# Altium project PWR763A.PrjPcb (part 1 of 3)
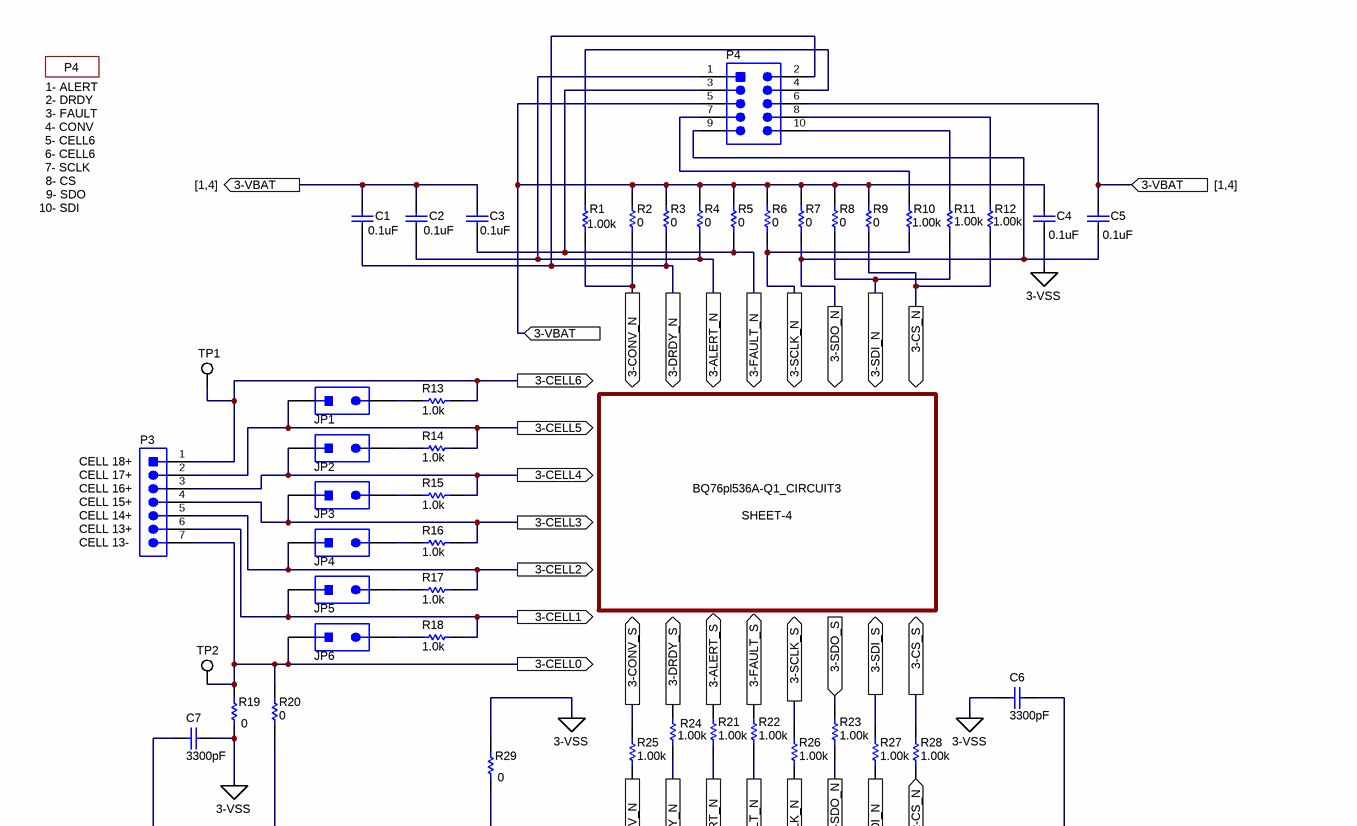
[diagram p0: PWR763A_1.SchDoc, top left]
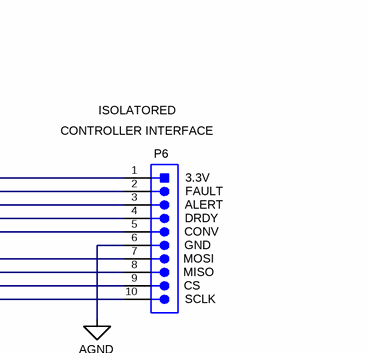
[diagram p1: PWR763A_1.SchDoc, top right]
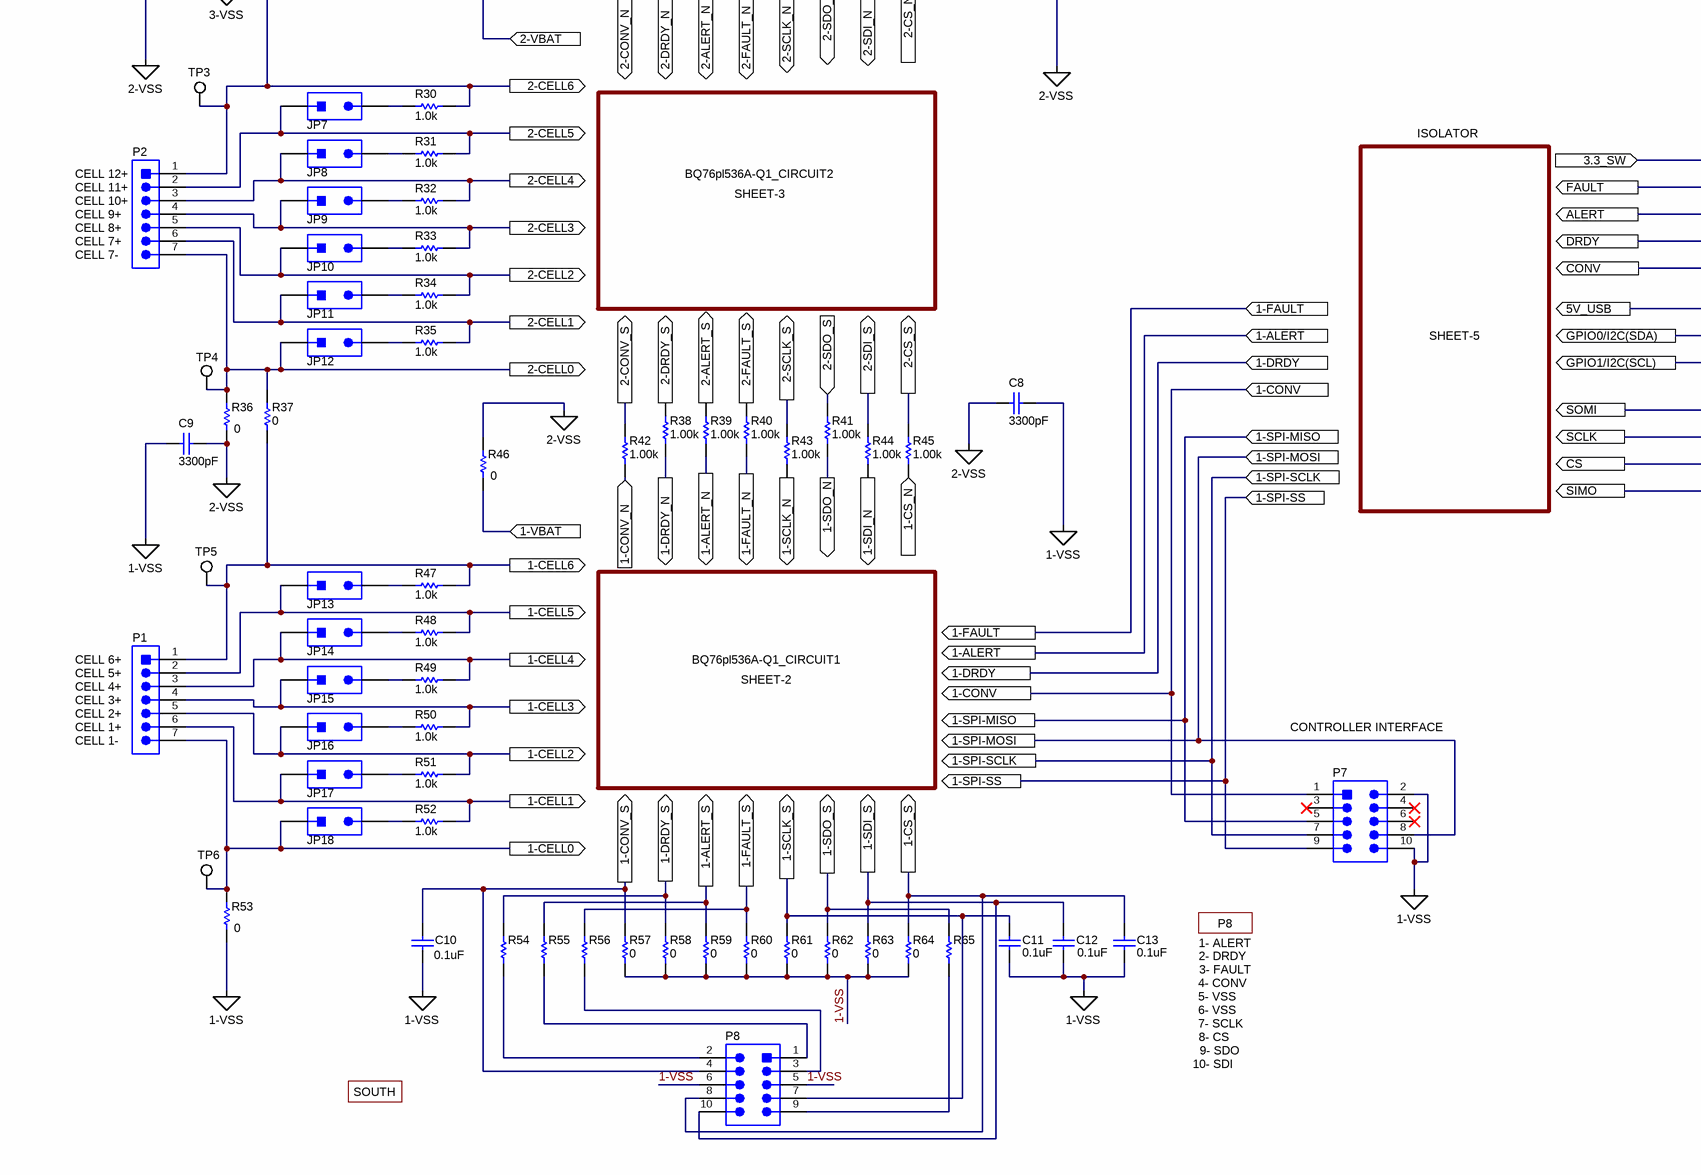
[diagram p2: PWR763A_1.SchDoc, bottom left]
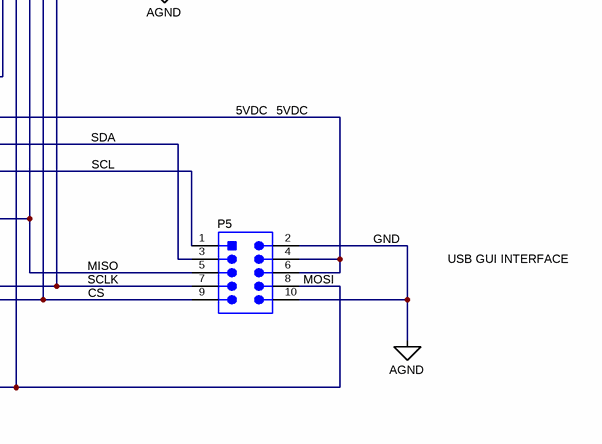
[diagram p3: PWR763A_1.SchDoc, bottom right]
TID: TID-00821; TechSupport: http://www.ti.com/support; SCH_Rev: A; PRJ_Title: PWR763; PRJ_Number: PWR763; PRJ_Engineer: Roger Hwang; PRJ_Customer: Public Release; PCB_Rev: A; PCB_Layout: Krypton-Solutions; EVM_Orderable: Bq76Pl536aQ1EVM763; CopyrightYear: 2015
6 sheets, 564 parts. Net scope: flat (ports and power ports of the same name join across sheets).
Board file: PWR763A.PcbDoc
Sheets:
  PWR763A_1.SchDoc
  PWR763A_2.SchDoc
  PWR763A_3.SchDoc
  PWR763A_4.SchDoc
  PWR763A_5.SchDoc
  PWR763A_Hardware.SchDoc

## Sheet PWR763A_1.SchDoc: PWR763A
size C; Date: Not shown in title block; ApprovedBy: Not shown in title block; CheckedBy: Not shown in title block; Author: Not shown in title block; CompanyName: Not shown in title block; Engineer: Not shown in title block; Organization: Not shown in title block; Address1: Not shown in title block; Address2: Not shown in title block; Address3: Not shown in title block; Address4: Not shown in title block; DocumentNumber: 1; Revision: Use project parameter SCH_Rev; SheetNumber: 1; SheetTotal: 6; PageSetup: Record=PageOptions¦CenterHorizontal=True¦CenterVertical=True¦PrintScale=1.00¦XCorrection=1.00¦YCorrection=1.00¦PrintKind=0¦BorderSize=5000000¦LeftOffset=0¦BottomOffset=0¦Orientation=2¦PaperLength=1000¦PaperWidth=1000¦Scale=100¦PaperSource=15¦PrintQuality=600¦MediaType=1¦DitherType=10¦PaperKind=Letter¦PrintScaleMode=1

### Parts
C1  value 0.1uF  [0603]  (hidden comment: 06035C104KAT2A)
C2  value 0.1uF  [0603]  (hidden comment: 06035C104KAT2A)
C3  value 0.1uF  [0603]  (hidden comment: 06035C104KAT2A)
C4  value 0.1uF  [0603]  (hidden comment: 06035C104KAT2A)
C5  value 0.1uF  [0603]  (hidden comment: 06035C104KAT2A)
C6  ValueDisplayed: 3300pF  [0603]  (hidden comment: GRM188R71H332KA01D)
C7  ValueDisplayed: 3300pF  [0603]  (hidden comment: GRM188R71H332KA01D)
C8  ValueDisplayed: 3300pF  [0603]  (hidden comment: GRM188R71H332KA01D)
C9  ValueDisplayed: 3300pF  [0603]  (hidden comment: GRM188R71H332KA01D)
C10  value 0.1uF  [0603]  (hidden comment: 06035C104KAT2A)
C11  value 0.1uF  [0603]  (hidden comment: 06035C104KAT2A)
C12  value 0.1uF  [0603]  (hidden comment: 06035C104KAT2A)
C13  value 0.1uF  [0603]  (hidden comment: 06035C104KAT2A)
JP1  PEC02SAAN  [CONN_PEC02SAAN]  (value not drawn)
JP2  PEC02SAAN  [CONN_PEC02SAAN]  (value not drawn)
JP3  PEC02SAAN  [CONN_PEC02SAAN]  (value not drawn)
JP4  PEC02SAAN  [CONN_PEC02SAAN]  (value not drawn)
JP5  PEC02SAAN  [CONN_PEC02SAAN]  (value not drawn)
JP6  PEC02SAAN  [CONN_PEC02SAAN]  (value not drawn)
JP7  PEC02SAAN  [CONN_PEC02SAAN]  (value not drawn)
JP8  PEC02SAAN  [CONN_PEC02SAAN]  (value not drawn)
JP9  PEC02SAAN  [CONN_PEC02SAAN]  (value not drawn)
JP10  PEC02SAAN  [CONN_PEC02SAAN]  (value not drawn)
JP11  PEC02SAAN  [CONN_PEC02SAAN]  (value not drawn)
JP12  PEC02SAAN  [CONN_PEC02SAAN]  (value not drawn)
JP13  PEC02SAAN  [CONN_PEC02SAAN]  (value not drawn)
JP14  PEC02SAAN  [CONN_PEC02SAAN]  (value not drawn)
JP15  PEC02SAAN  [CONN_PEC02SAAN]  (value not drawn)
JP16  PEC02SAAN  [CONN_PEC02SAAN]  (value not drawn)
JP17  PEC02SAAN  [CONN_PEC02SAAN]  (value not drawn)
JP18  PEC02SAAN  [CONN_PEC02SAAN]  (value not drawn)
P1  395021007  [Molex_395021007]  (value not drawn)
P2  395021007  [Molex_395021007]  (value not drawn)
P3  395021007  [Molex_395021007]  (value not drawn)
P4  5103308-1  [CONN_5103308-1]  (value not drawn)
P5  5103308-1  [CONN_5103308-1]  (value not drawn)
P6  HPM-10-05-T-S  [Samtec_HPM-10-05-T-S]  (value not drawn)
P7  5103308-1  [CONN_5103308-1]  (value not drawn)
P8  5103308-1  [CONN_5103308-1]  (value not drawn)
R1  value 1.00k  [1206]  (hidden comment: CRCW12061K00FKEA)
R2  ValueDisplayed: 0  [0603]  (hidden comment: CRCW06030000Z0EA)
R3  ValueDisplayed: 0  [0603]  (hidden comment: CRCW06030000Z0EA)
R4  ValueDisplayed: 0  [0603]  (hidden comment: CRCW06030000Z0EA)
R5  ValueDisplayed: 0  [0603]  (hidden comment: CRCW06030000Z0EA)
R6  ValueDisplayed: 0  [0603]  (hidden comment: CRCW06030000Z0EA)
R7  ValueDisplayed: 0  [0603]  (hidden comment: CRCW06030000Z0EA)
R8  ValueDisplayed: 0  [0603]  (hidden comment: CRCW06030000Z0EA)
R9  ValueDisplayed: 0  [0603]  (hidden comment: CRCW06030000Z0EA)
R10  value 1.00k  [1206]  (hidden comment: CRCW12061K00FKEA)
R11  value 1.00k  [1206]  (hidden comment: CRCW12061K00FKEA)
R12  value 1.00k  [1206]  (hidden comment: CRCW12061K00FKEA)
R13  ValueDisplayed: 1.0k  [0603]  (hidden comment: CRCW06031K00JNEA)
R14  ValueDisplayed: 1.0k  [0603]  (hidden comment: CRCW06031K00JNEA)
R15  ValueDisplayed: 1.0k  [0603]  (hidden comment: CRCW06031K00JNEA)
R16  ValueDisplayed: 1.0k  [0603]  (hidden comment: CRCW06031K00JNEA)
R17  ValueDisplayed: 1.0k  [0603]  (hidden comment: CRCW06031K00JNEA)
R18  ValueDisplayed: 1.0k  [0603]  (hidden comment: CRCW06031K00JNEA)
R19  ValueDisplayed: 0  [1206]  (hidden comment: CRCW12060000Z0EA)
R20  ValueDisplayed: 0  [0603]  (hidden comment: CRCW06030000Z0EA)
R21  ValueDisplayed: 1.00k  [0603]  (hidden comment: RG1608P-102-B-T5)
R22  ValueDisplayed: 1.00k  [0603]  (hidden comment: RG1608P-102-B-T5)
R23  ValueDisplayed: 1.00k  [0603]  (hidden comment: RG1608P-102-B-T5)
R24  ValueDisplayed: 1.00k  [0603]  (hidden comment: RG1608P-102-B-T5)
R25  ValueDisplayed: 1.00k  [0603]  (hidden comment: RG1608P-102-B-T5)
R26  ValueDisplayed: 1.00k  [0603]  (hidden comment: RG1608P-102-B-T5)
R27  ValueDisplayed: 1.00k  [0603]  (hidden comment: RG1608P-102-B-T5)
R28  ValueDisplayed: 1.00k  [0603]  (hidden comment: RG1608P-102-B-T5)
R29  ValueDisplayed: 0  [1206]  (hidden comment: CRCW12060000Z0EA)
R30  ValueDisplayed: 1.0k  [0603]  (hidden comment: CRCW06031K00JNEA)
R31  ValueDisplayed: 1.0k  [0603]  (hidden comment: CRCW06031K00JNEA)
R32  ValueDisplayed: 1.0k  [0603]  (hidden comment: CRCW06031K00JNEA)
R33  ValueDisplayed: 1.0k  [0603]  (hidden comment: CRCW06031K00JNEA)
R34  ValueDisplayed: 1.0k  [0603]  (hidden comment: CRCW06031K00JNEA)
R35  ValueDisplayed: 1.0k  [0603]  (hidden comment: CRCW06031K00JNEA)
R36  ValueDisplayed: 0  [1206]  (hidden comment: CRCW12060000Z0EA)
R37  ValueDisplayed: 0  [0603]  (hidden comment: CRCW06030000Z0EA)
R38  ValueDisplayed: 1.00k  [0603]  (hidden comment: RG1608P-102-B-T5)
R39  ValueDisplayed: 1.00k  [0603]  (hidden comment: RG1608P-102-B-T5)
R40  ValueDisplayed: 1.00k  [0603]  (hidden comment: RG1608P-102-B-T5)
R41  ValueDisplayed: 1.00k  [0603]  (hidden comment: RG1608P-102-B-T5)
R42  ValueDisplayed: 1.00k  [0603]  (hidden comment: RG1608P-102-B-T5)
R43  ValueDisplayed: 1.00k  [0603]  (hidden comment: RG1608P-102-B-T5)
R44  ValueDisplayed: 1.00k  [0603]  (hidden comment: RG1608P-102-B-T5)
R45  ValueDisplayed: 1.00k  [0603]  (hidden comment: RG1608P-102-B-T5)
R46  ValueDisplayed: 0  [1206]  (hidden comment: CRCW12060000Z0EA)
R47  ValueDisplayed: 1.0k  [0603]  (hidden comment: CRCW06031K00JNEA)
R48  ValueDisplayed: 1.0k  [0603]  (hidden comment: CRCW06031K00JNEA)
R49  ValueDisplayed: 1.0k  [0603]  (hidden comment: CRCW06031K00JNEA)
R50  ValueDisplayed: 1.0k  [0603]  (hidden comment: CRCW06031K00JNEA)
R51  ValueDisplayed: 1.0k  [0603]  (hidden comment: CRCW06031K00JNEA)
R52  ValueDisplayed: 1.0k  [0603]  (hidden comment: CRCW06031K00JNEA)
R53  ValueDisplayed: 0  [1206]  (hidden comment: CRCW12060000Z0EA)
R54  CRCW12061K00FKEA  [1206]  (value not drawn)
R55  CRCW12061K00FKEA  [1206]  (value not drawn)
R56  CRCW12061K00FKEA  [1206]  (value not drawn)
R57  ValueDisplayed: 0  [0603]  (hidden comment: CRCW06030000Z0EA)
R58  ValueDisplayed: 0  [0603]  (hidden comment: CRCW06030000Z0EA)
R59  ValueDisplayed: 0  [0603]  (hidden comment: CRCW06030000Z0EA)
R60  ValueDisplayed: 0  [0603]  (hidden comment: CRCW06030000Z0EA)
R61  ValueDisplayed: 0  [0603]  (hidden comment: CRCW06030000Z0EA)
R62  ValueDisplayed: 0  [0603]  (hidden comment: CRCW06030000Z0EA)
R63  ValueDisplayed: 0  [0603]  (hidden comment: CRCW06030000Z0EA)
R64  ValueDisplayed: 0  [0603]  (hidden comment: CRCW06030000Z0EA)
R65  CRCW12061K00FKEA  [1206]  (value not drawn)
TP1  5015  [Testpoint_Keystone_Miniature]  (value not drawn)
TP2  5015  [Testpoint_Keystone_Miniature]  (value not drawn)
TP3  5015  [Testpoint_Keystone_Miniature]  (value not drawn)
TP4  5015  [Testpoint_Keystone_Miniature]  (value not drawn)
TP5  5015  [Testpoint_Keystone_Miniature]  (value not drawn)
TP6  5015  [Testpoint_Keystone_Miniature]  (value not drawn)

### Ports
1-ALERT, 1-ALERT_N, 1-ALERT_S, 1-CELL0, 1-CELL1, 1-CELL2, 1-CELL3, 1-CELL4, 1-CELL5, 1-CELL6, 1-CONV, 1-CONV_N (in), 1-CONV_S, 1-CS_N, 1-CS_S, 1-DRDY, 1-DRDY_N, 1-DRDY_S, 1-FAULT, 1-FAULT_N, 1-FAULT_S, 1-SCLK_N (in), 1-SCLK_S, 1-SDI_N (in), 1-SDI_S, 1-SDO_N (out), 1-SDO_S, 1-SPI-MISO, 1-SPI-MOSI, 1-SPI-SCLK, 1-SPI-SS, 1-VBAT, 2-ALERT_N, 2-ALERT_S (in), 2-CELL0, 2-CELL1, 2-CELL2, 2-CELL3, 2-CELL4, 2-CELL5, 2-CELL6, 2-CONV_N (in), 2-CONV_S, 2-CS_N (in), 2-CS_S, 2-DRDY_N, 2-DRDY_S (in), 2-FAULT_N, 2-FAULT_S (in), 2-SCLK_N (in), 2-SCLK_S, 2-SDI_N (in), 2-SDI_S, 2-SDO_N (out), 2-SDO_S (in), 2-VBAT, 3-ALERT_N, 3-ALERT_S (in), 3-CELL0, 3-CELL1, 3-CELL2, 3-CELL3, 3-CELL4, 3-CELL5, 3-CELL6, 3-CONV_N, 3-CONV_S, 3-CS_N (out), 3-CS_S, 3-DRDY_N, 3-DRDY_S (in), 3-FAULT_N, 3-FAULT_S (in), 3-SCLK_N (out), 3-SCLK_S, 3-SDI_N, 3-SDI_S, 3-SDO_N (out), 3-SDO_S (in), 3-VBAT, 3.3_SW, 5V_USB, ALERT, CONV, CS, DRDY, FAULT, GPIO0/I2C(SDA), GPIO1/I2C(SCL), SCLK, SIMO, SOMI

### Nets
1-VSS: C8.1 C9.2 C10.2 C11.2 C12.2 C13.2 JP18.1 P1.7 P7.2 P7.10 P8.5 P8.6 R53.1 R53.2 R57.1 R58.1 R59.1 R60.1 R61.1 R62.1 R63.1 R64.1 TP6.1 ; port 1-CELL0  [project net 1-VC0]
2-VSS: C6.1 C7.2 C8.2 C9.1 JP12.1 P2.7 R36.1 R36.2 R37.2 R46.2 TP4.1 ; port 2-CELL0  [project net 2-VC0]
3-VSS: C4.2 C6.2 C7.1 JP6.1 P3.7 R19.1 R19.2 R20.2 R29.2 TP2.1 ; port 3-CELL0  [project net 3-VC0]
AGND: P5.2 P5.10 P6.6
1-ALERT_N: R39.1 ; port 1-ALERT_N
1-ALERT_S: R55.2 R59.2 ; port 1-ALERT_S
1-CELL1: JP17.1 P1.6 R52.2 ; port 1-CELL1
1-CELL2: JP16.1 P1.5 R51.2 ; port 1-CELL2
1-CELL3: JP15.1 P1.4 R50.2 ; port 1-CELL3
1-CELL4: JP14.1 P1.3 R49.2 ; port 1-CELL4
1-CELL5: JP13.1 P1.2 R48.2 ; port 1-CELL5
1-CELL6: P1.1 R37.1 R47.2 TP5.1 ; port 1-CELL6
1-CONV: P7.1 ; port 1-CONV
1-CONV_N: R42.1 ; port 1-CONV_N
1-CONV_S: C10.1 P8.4 R57.2 ; port 1-CONV_S
1-CS_N: R45.1 ; port 1-CS_N
1-CS_S: C13.1 P8.8 R64.2 ; port 1-CS_S
1-DRDY_N: R38.1 ; port 1-DRDY_N
1-DRDY_S: R54.2 R58.2 ; port 1-DRDY_S
1-FAULT_N: R40.1 ; port 1-FAULT_N
1-FAULT_S: R56.2 R60.2 ; port 1-FAULT_S
1-SCLK_N: R43.1 ; port 1-SCLK_N
1-SCLK_S: C11.1 P8.7 R61.2 ; port 1-SCLK_S
1-SDI_N: R44.1 ; port 1-SDI_N
1-SDI_S: C12.1 P8.10 R63.2 ; port 1-SDI_S
1-SDO_N: R41.1 ; port 1-SDO_N
1-SDO_S: R62.2 R65.2 ; port 1-SDO_S
1-SPI-MISO: P7.5 ; port 1-SPI-MISO
1-SPI-MOSI: P7.8 ; port 1-SPI-MOSI
1-SPI-SCLK: P7.7 ; port 1-SPI-SCLK
1-SPI-SS: P7.9 ; port 1-SPI-SS
1-VBAT: R46.1 ; port 1-VBAT
2-ALERT_N: R21.1 ; port 2-ALERT_N
2-ALERT_S: R39.2 ; port 2-ALERT_S
2-CELL1: JP11.1 P2.6 R35.2 ; port 2-CELL1
2-CELL2: JP10.1 P2.5 R34.2 ; port 2-CELL2
2-CELL3: JP9.1 P2.4 R33.2 ; port 2-CELL3
2-CELL4: JP8.1 P2.3 R32.2 ; port 2-CELL4
2-CELL5: JP7.1 P2.2 R31.2 ; port 2-CELL5
2-CELL6: P2.1 R20.1 R30.2 TP3.1 ; port 2-CELL6
2-CONV_N: R25.1 ; port 2-CONV_N
2-CONV_S: R42.2 ; port 2-CONV_S
2-CS_N: R28.1 ; port 2-CS_N
2-CS_S: R45.2 ; port 2-CS_S
2-DRDY_N: R24.1 ; port 2-DRDY_N
2-DRDY_S: R38.2 ; port 2-DRDY_S
2-FAULT_N: R22.1 ; port 2-FAULT_N
2-FAULT_S: R40.2 ; port 2-FAULT_S
2-SCLK_N: R26.1 ; port 2-SCLK_N
2-SCLK_S: R43.2 ; port 2-SCLK_S
2-SDI_N: R27.1 ; port 2-SDI_N
2-SDI_S: R44.2 ; port 2-SDI_S
2-SDO_N: R23.1 ; port 2-SDO_N
2-SDO_S: R41.2 ; port 2-SDO_S
2-VBAT: R29.1 ; port 2-VBAT
3-ALERT_N: C2.2 P4.1 R4.1 ; port 3-ALERT_N
3-ALERT_S: R21.2 ; port 3-ALERT_S
3-CELL1: JP5.1 P3.6 R18.2 ; port 3-CELL1
3-CELL2: JP4.1 P3.5 R17.2 ; port 3-CELL2
3-CELL3: JP3.1 P3.4 R16.2 ; port 3-CELL3
3-CELL4: JP2.1 P3.3 R15.2 ; port 3-CELL4
3-CELL5: JP1.1 P3.2 R14.2 ; port 3-CELL5
3-CELL6: P3.1 R13.2 TP1.1 ; port 3-CELL6
3-CONV_N: R1.1 R2.1 ; port 3-CONV_N
3-CONV_S: R25.2 ; port 3-CONV_S
3-CS_N: R9.1 R12.1 ; port 3-CS_N
3-CS_S: R28.2 ; port 3-CS_S
3-DRDY_N: C1.2 P4.2 R3.1 ; port 3-DRDY_N
3-DRDY_S: R24.2 ; port 3-DRDY_S
3-FAULT_N: C3.2 P4.3 R5.1 ; port 3-FAULT_N
3-FAULT_S: R22.2 ; port 3-FAULT_S
3-SCLK_N: R6.1 R10.1 ; port 3-SCLK_N
3-SCLK_S: R26.2 ; port 3-SCLK_S
3-SDI_N: R8.1 R11.1 ; port 3-SDI_N
3-SDI_S: R27.2 ; port 3-SDI_S
3-SDO_N: C5.2 P4.9 R7.1 ; port 3-SDO_N
3-SDO_S: R23.2 ; port 3-SDO_S
3-VBAT: C1.1 C2.1 C3.1 C4.1 C5.1 P4.5 P4.6 R2.2 R3.2 R4.2 R5.2 R6.2 R7.2 R8.2 R9.2 ; port 3-VBAT
3.3_SW: P6.1 ; port 3.3_SW
5V_USB: P5.4 P5.6 ; port 5V_USB
ALERT: P6.3 ; port ALERT
CONV: P6.5 ; port CONV
CS: P5.9 P6.9 ; port CS
DRDY: P6.4 ; port DRDY
FAULT: P6.2 ; port FAULT
GPIO0/I2C(SDA): P5.3 ; port GPIO0/I2C(SDA)
GPIO1/I2C(SCL): P5.1 ; port GPIO1/I2C(SCL)
SCLK: P5.7 P6.10 ; port SCLK
SIMO: P5.8 P6.7 ; port SIMO
SOMI: P5.5 P6.8 ; port SOMI
NetJP1_2: JP1.2 R13.1
NetJP2_2: JP2.2 R14.1
NetJP3_2: JP3.2 R15.1
NetJP4_2: JP4.2 R16.1
NetJP5_2: JP5.2 R17.1
NetJP6_2: JP6.2 R18.1
NetJP7_2: JP7.2 R30.1
NetJP8_2: JP8.2 R31.1
NetJP9_2: JP9.2 R32.1
NetJP10_2: JP10.2 R33.1
NetJP11_2: JP11.2 R34.1
NetJP12_2: JP12.2 R35.1
NetJP13_2: JP13.2 R47.1
NetJP14_2: JP14.2 R48.1
NetJP15_2: JP15.2 R49.1
NetJP16_2: JP16.2 R50.1
NetJP17_2: JP17.2 R51.1
NetJP18_2: JP18.2 R52.1
NetP4_4: P4.4 R1.2
NetP4_7: P4.7 R10.2
NetP4_8: P4.8 R12.2
NetP4_10: P4.10 R11.2
NetP8_1: P8.1 R55.1
NetP8_2: P8.2 R54.1
NetP8_3: P8.3 R56.1
NetP8_9: P8.9 R65.1

Not connected (* = marked no-connect by the designer): P7 3* 4* 6*

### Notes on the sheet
- P4
- 2- DRDY
- 4- CONV
- 5- CELL6
- 1- ALERT
- 3- FAULT
- 10- SDI
- 8- CS
- 9- SDO
- 7- SCLK
- 6- CELL6
- [1,4]
- (near P3) CELL 17+
- (near P3) CELL 18+
- (near P3) CELL 13-
- (near P3) CELL 13+
- (near P3) CELL 14+
- (near P3) CELL 15+
- (near P3) CELL 16+
- BQ76pl536A-Q1_CIRCUIT3
- SHEET-4
- ISOLATORED
- (near P6) CONTROLLER INTERFACE
- (near P6) 3.3V
- (near P6) DRDY
- (near P6) CONV
- (near P6) FAULT
- (near P6) ALERT
- ISOLATOR
- (near P6) CS
- (near P6) GND
- (near P6) MOSI
- (near P6) MISO
- (near P6) SCLK
- (near P2) CELL 8+
- (near P2) CELL 9+
- (near P2) CELL 10+
- (near P2) CELL 11+
- (near P2) CELL 12+
- BQ76pl536A-Q1_CIRCUIT2
- SHEET-3
- (near P2) CELL 7-
- (near P2) CELL 7+
- 5VDC
- SHEET-5
- SCL
- SDA
- GND
- CS
- SCLK
- MISO
- (near P5) MOSI
- USB GUI INTERFACE
- (near P1) CELL 3+
- (near P1) CELL 4+
- (near P1) CELL 5+
- (near P1) CELL 6+
- BQ76pl536A-Q1_CIRCUIT1
- SHEET-2
- (near P1) CELL 1-
- (near P1) CELL 1+
- (near P1) CELL 2+
- CONTROLLER INTERFACE
- P8
- 5- VSS
- 6- VSS
- SOUTH

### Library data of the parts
C1-C5 C10-C13 = 06035C104KAT2A: CAP, CERM, 0.1 µF, 50 V, +/- 10%, X7R, 0603; Manufacturer: AVX; Polarized: N; CompType: Capacitor; ValueDisplayed: 0.1µF; U/M: EA; Cap_F: 0.0000001; Tolerance_%: 10; Value1: Unknown; VDC_V: 50; Value2: 50V; TaMin_C: -55; TaMax_C: 125
C6-C9 = GRM188R71H332KA01D: CAP, CERM, 3300 pF, 50 V, +/- 10%, X7R, 0603; Manufacturer: MuRata; Polarized: N; CompType: Capacitor; Value: 3300pF; U/M: EA; Cap_F: 0.0000000033; Tolerance_%: 10; Value1: Unknown; VDC_V: 50; Value2: 50V; TaMin_C: -55; TaMax_C: 125
JP1-JP18 = PEC02SAAN: Header, 100mil, 2x1, Tin, TH; Manufacturer: Sullins Connector Solutions; SymbolCreator: a0412235; U/M: EA
P1-P3 = 395021007: Header(Shrouded), 3.5mm, 7x1,  R/A, TH; Manufacturer: Molex; SymbolCreator: a0411947; U/M: EA
P4 P5 P7 P8 = 5103308-1: Header (shrouded), 100mil, 5x2, Gold, TH; Manufacturer: TE Connectivity; SymbolCreator: a0412235; U/M: EA
P6 = HPM-10-05-T-S: Header, 5.08mm, 10x1, Tin, TH; Manufacturer: Samtec; SymbolCreator: a0412235; U/M: EA
R1 R10-R12 = CRCW12061K00FKEA: RES, 1.00 k, 1%, 0.25 W, 1206; Manufacturer: Vishay-Dale; CompType: Resistor; Res_ohm: 1000; Value_Code: 1k00; Tolerance_%: 1; Power_W: 0.25; Value2: 0.25W; VDC_V: 200; TempCo: 100 ppm/C; EIA_Code: E96; U/M: EA
R2-R9 R20 R37 R57-R64 = CRCW06030000Z0EA: RES, 0, 5%, 0.1 W, 0603; Manufacturer: Vishay-Dale; CompType: Resistor; Value: 0; Value_Code: 0000; Tolerance_%: 5; Power_W: 0.1; Value2: 0.1W; VDC_V: 75; TempCo: 200 ppm/C; EIA_Code: E24; U/M: EA
R13-R18 R30-R35 R47-R52 = CRCW06031K00JNEA: RES, 1.0 k, 5%, 0.1 W, 0603; Manufacturer: Vishay-Dale; CompType: Resistor; Value: 1.0k; Res_ohm: 1000; Value_Code: 1k00; Tolerance_%: 5; Power_W: 0.1; Value2: 0.1W; VDC_V: 75; TempCo: 200 ppm/C; EIA_Code: E24; U/M: EA
R19 R29 R36 R46 R53 = CRCW12060000Z0EA: RES, 0, 5%, 0.25 W, 1206; Manufacturer: Vishay-Dale; CompType: Resistor; Value: 0; Value_Code: 0000; Tolerance_%: 5; Power_W: 0.25; Value2: 0.25W; VDC_V: 200; TempCo: 200 ppm/C; EIA_Code: E24; U/M: EA
R21-R28 R38-R45 = RG1608P-102-B-T5: RES, 1.00 k, 0.1%, 0.1 W, 0603; Manufacturer: Susumu Co Ltd; CompType: Resistor; Value: 1.00k; Res_ohm: 1000; Value_Code: 1k00; Tolerance_%: 0.1; Value2: 0.1W; VDC_V: 75; TempCo: 25 ppm/C; EIA_Code: E192; U/M: EA
R54-R56 R65 = CRCW12061K00FKEA: RES, 1.00 k, 1%, 0.25 W, 1206; Manufacturer: Vishay-Dale; CompType: Resistor; Value: 1.00k; Res_ohm: 1000; Value_Code: 1k00; Tolerance_%: 1; Power_W: 0.25; Value2: 0.25W; VDC_V: 200; TempCo: 100 ppm/C; EIA_Code: E96; U/M: EA
TP1-TP6 = 5015: Test Point, Miniature, SMT; Manufacturer: Keystone; CompType: Test Point Loop; U/M: EA

## Sheet PWR763A_2.SchDoc: PWR763A
size 431 x 279 mm; Date: Not shown in title block; ApprovedBy: Not shown in title block; CheckedBy: Not shown in title block; Author: Not shown in title block; CompanyName: Not shown in title block; Engineer: Not shown in title block; Organization: Not shown in title block; Address1: Not shown in title block; Address2: Not shown in title block; Address3: Not shown in title block; Address4: Not shown in title block; DocumentNumber: 1; Revision: Use project parameter SCH_Rev; SheetNumber: 2; SheetTotal: 6; PageSetup: Record=PageOptions¦CenterHorizontal=True¦CenterVertical=True¦PrintScale=1.00¦XCorrection=1.00¦YCorrection=1.00¦PrintKind=0¦BorderSize=5000000¦LeftOffset=0¦BottomOffset=0¦Orientation=2¦PaperLength=1000¦PaperWidth=1000¦Scale=100¦PaperSource=15¦PrintQuality=600¦MediaType=1¦DitherType=10¦PaperKind=Letter¦PrintScaleMode=1
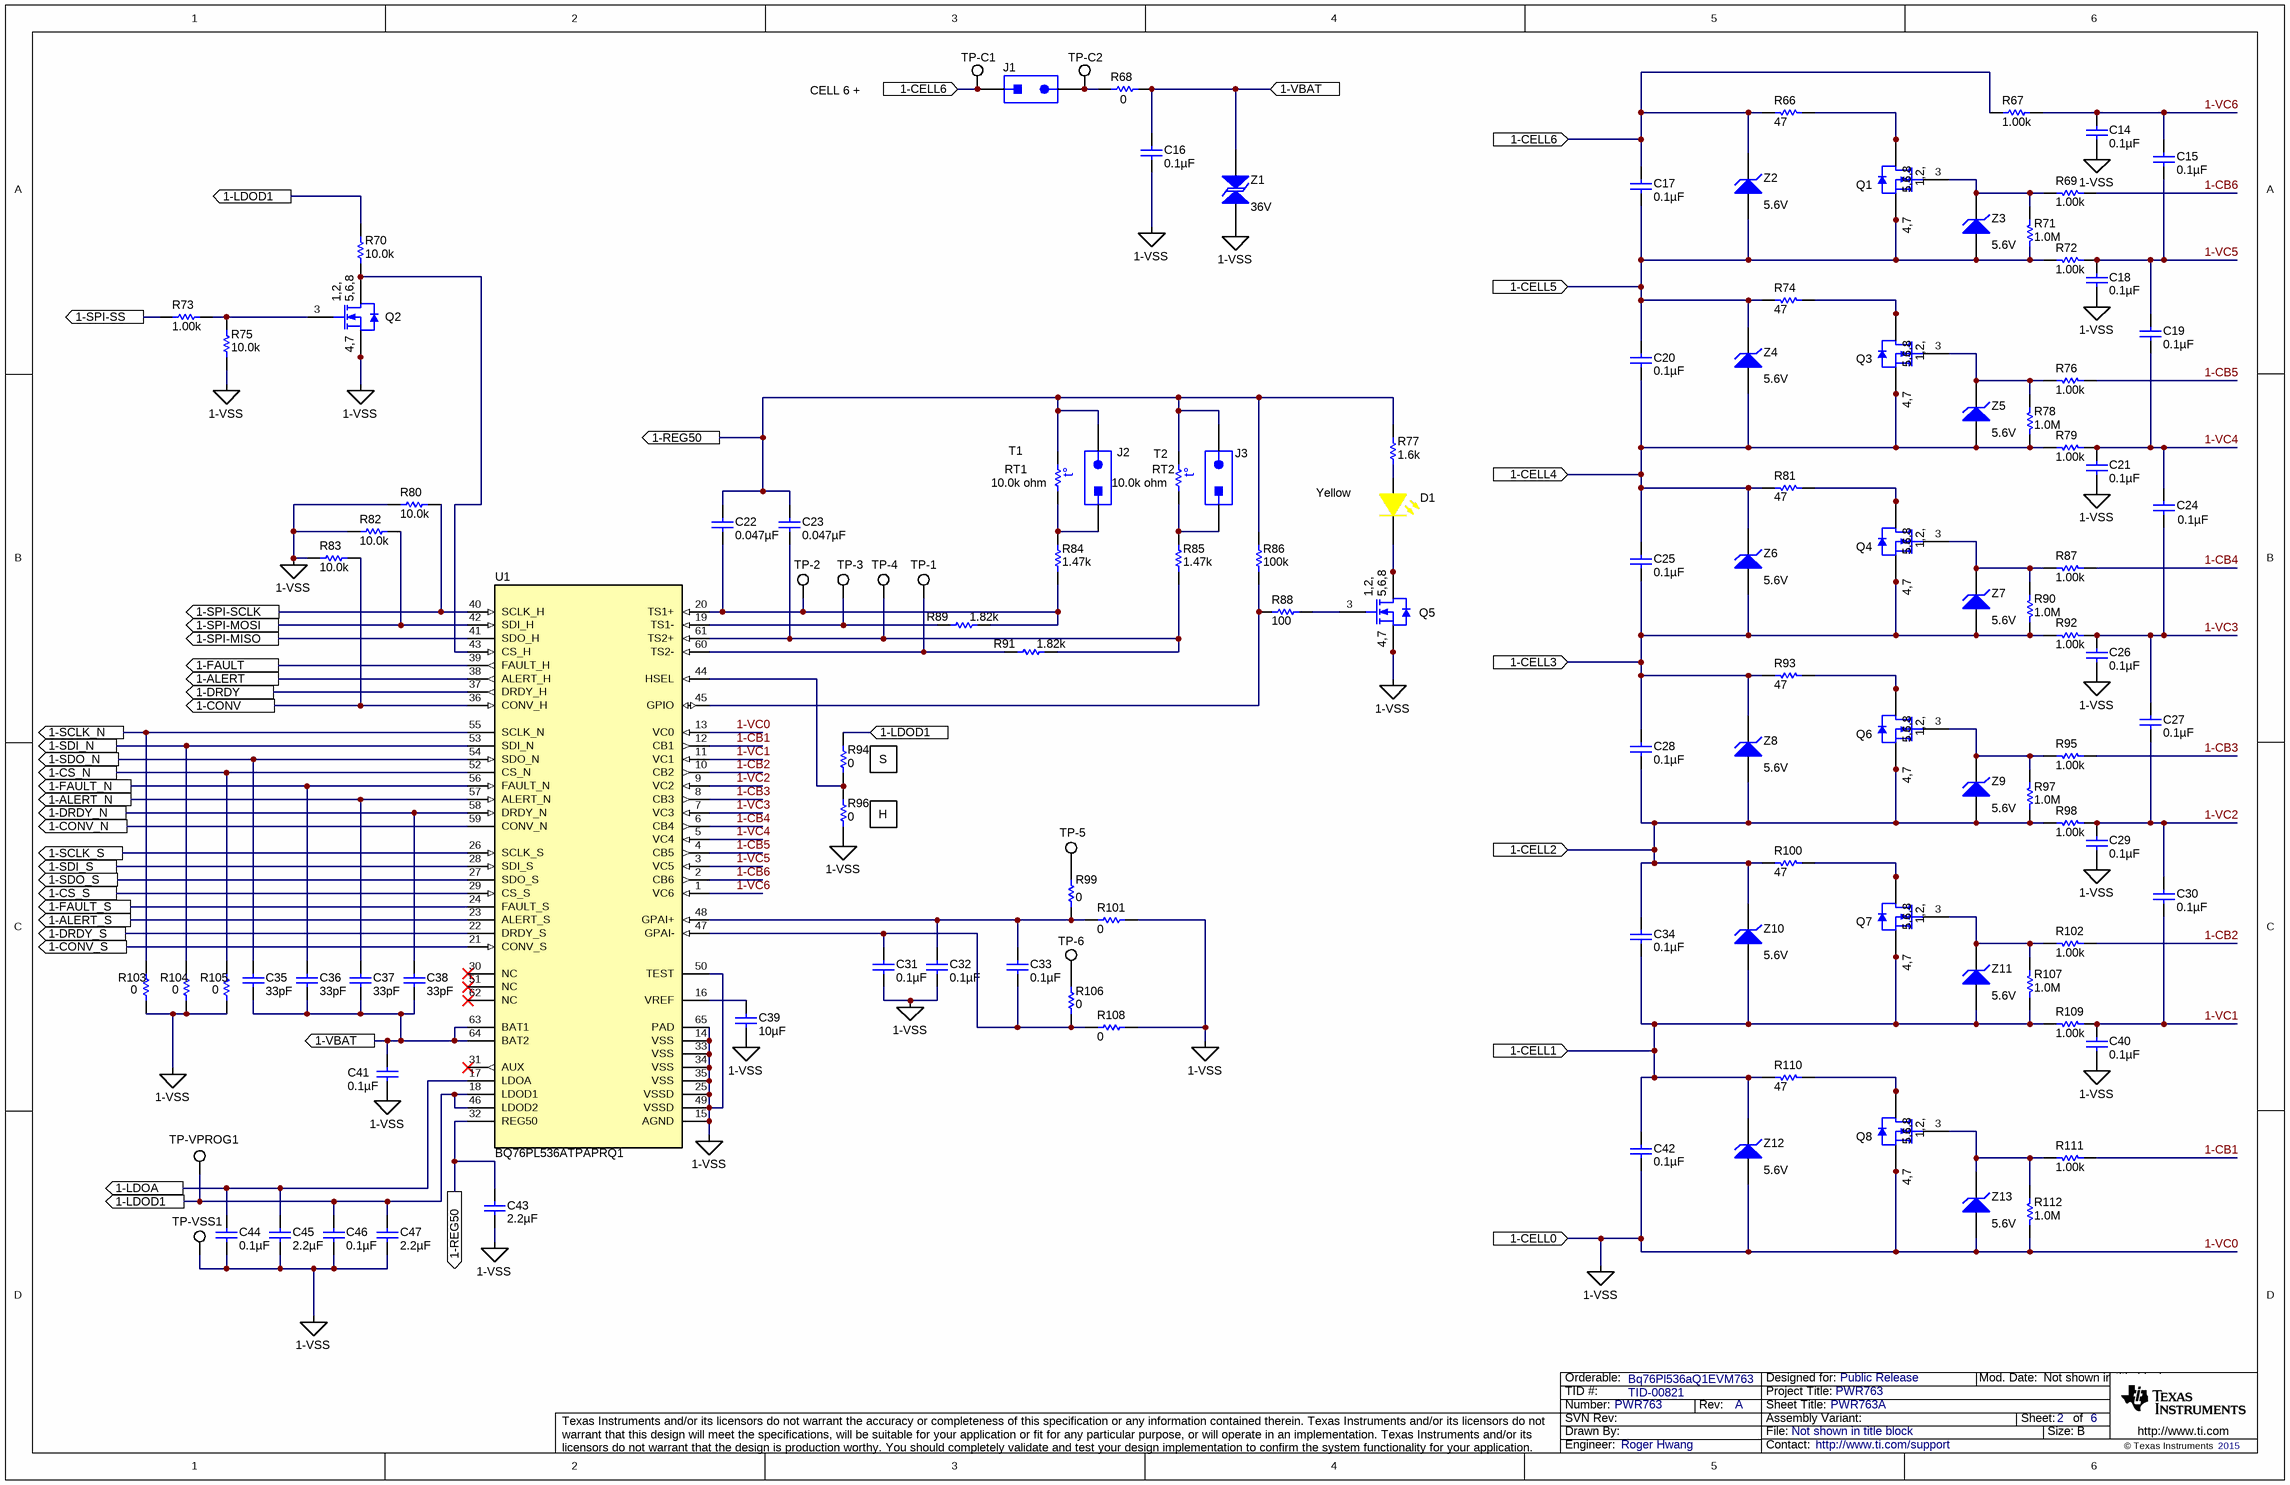
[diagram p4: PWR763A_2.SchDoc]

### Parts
C14  ValueDisplayed: 0.1µF  [0603]  (hidden comment: 06035C104KAT2A)
C15  ValueDisplayed: 0.1µF  [0603]  (hidden comment: GRM188R72A104KA35D)
C16  ValueDisplayed: 0.1µF  [0603]  (hidden comment: GRM188R72A104KA35D)
C17  ValueDisplayed: 0.1µF  [0603]  (hidden comment: 06035C104KAT2A)
C18  ValueDisplayed: 0.1µF  [0603]  (hidden comment: 06035C104KAT2A)
C19  ValueDisplayed: 0.1µF  [0603]  (hidden comment: GRM188R72A104KA35D)
C20  ValueDisplayed: 0.1µF  [0603]  (hidden comment: 06035C104KAT2A)
C21  ValueDisplayed: 0.1µF  [0603]  (hidden comment: 06035C104KAT2A)
C22  ValueDisplayed: 0.047µF  [0603]  (hidden comment: GRM188R71C473KA01D)
C23  ValueDisplayed: 0.047µF  [0603]  (hidden comment: GRM188R71C473KA01D)
C24  ValueDisplayed: 0.1µF  [0603]  (hidden comment: GRM188R72A104KA35D)
C25  ValueDisplayed: 0.1µF  [0603]  (hidden comment: 06035C104KAT2A)
C26  ValueDisplayed: 0.1µF  [0603]  (hidden comment: 06035C104KAT2A)
C27  ValueDisplayed: 0.1µF  [0603]  (hidden comment: GRM188R72A104KA35D)
C28  ValueDisplayed: 0.1µF  [0603]  (hidden comment: 06035C104KAT2A)
C29  ValueDisplayed: 0.1µF  [0603]  (hidden comment: 06035C104KAT2A)
C30  ValueDisplayed: 0.1µF  [0603]  (hidden comment: GRM188R72A104KA35D)
C31  ValueDisplayed: 0.1µF  [0603]  (hidden comment: C0603C104K4RACTU)
C32  ValueDisplayed: 0.1µF  [0603]  (hidden comment: C0603C104K4RACTU)
C33  ValueDisplayed: 0.1µF  [0603]  (hidden comment: C0603C104K4RACTU)
C34  ValueDisplayed: 0.1µF  [0603]  (hidden comment: GRM188R72A104KA35D)
C35  ValueDisplayed: 33pF  [0603]  (hidden comment: GRM1885C1H330JA01D)
C36  ValueDisplayed: 33pF  [0603]  (hidden comment: GRM1885C1H330JA01D)
C37  ValueDisplayed: 33pF  [0603]  (hidden comment: GRM1885C1H330JA01D)
C38  ValueDisplayed: 33pF  [0603]  (hidden comment: GRM1885C1H330JA01D)
C39  ValueDisplayed: 10µF  [0805_145]  (hidden comment: C2012X7R1A106M125AC)
C40  ValueDisplayed: 0.1µF  [0603]  (hidden comment: 06035C104KAT2A)
C41  ValueDisplayed: 0.1µF  [0603]  (hidden comment: 06035C104KAT2A)
C42  ValueDisplayed: 0.1µF  [0603]  (hidden comment: 06035C104KAT2A)
C43  ValueDisplayed: 2.2µF  [0805_HV]  (hidden comment: GRM21BR71A225KA01L)
C44  ValueDisplayed: 0.1µF  [0603]  (hidden comment: 06035C104KAT2A)
C45  ValueDisplayed: 2.2µF  [0805_HV]  (hidden comment: GRM21BR71A225KA01L)
C46  ValueDisplayed: 0.1µF  [0603]  (hidden comment: 06035C104KAT2A)
C47  ValueDisplayed: 2.2µF  [0805_HV]  (hidden comment: GRM21BR71A225KA01L)
D1  value Yellow  [APT1608_Yellow]  (hidden comment: APT1608SYCK)
J1  PEC02SAAN  [CONN_PEC02SAAN]  (value not drawn)
J2  PEC02SAAN  [CONN_PEC02SAAN]  (value not drawn)
J3  PEC02SAAN  [CONN_PEC02SAAN]  (value not drawn)
Q1  CSD16301Q2  [TRANS_NexFET_Q2]  (value not drawn)
Q2  CSD16301Q2  [TRANS_NexFET_Q2]  (value not drawn)
Q3  CSD16301Q2  [TRANS_NexFET_Q2]  (value not drawn)
Q4  CSD16301Q2  [TRANS_NexFET_Q2]  (value not drawn)
Q5  CSD16301Q2  [TRANS_NexFET_Q2]  (value not drawn)
Q6  CSD16301Q2  [TRANS_NexFET_Q2]  (value not drawn)
Q7  CSD16301Q2  [TRANS_NexFET_Q2]  (value not drawn)
Q8  CSD16301Q2  [TRANS_NexFET_Q2]  (value not drawn)
R66  ValueDisplayed: 47  [2512]  (hidden comment: CRCW251247R0JNEG)
R67  ValueDisplayed: 1.00k  [0603]  (hidden comment: RG1608P-102-B-T5)
R68  ValueDisplayed: 0  [0805_HV]  (hidden comment: CRCW08050000Z0EA)
R69  ValueDisplayed: 1.00k  [0603]  (hidden comment: RG1608P-102-B-T5)
R70  ValueDisplayed: 10.0k  [0603]  (hidden comment: ERJ-3EKF1002V)
R71  ValueDisplayed: 1.0M  [0603]  (hidden comment: CRCW06031M00JNEA)
R72  ValueDisplayed: 1.00k  [0603]  (hidden comment: RG1608P-102-B-T5)
R73  ValueDisplayed: 1.00k  [0603]  (hidden comment: RG1608P-102-B-T5)
R74  ValueDisplayed: 47  [2512]  (hidden comment: CRCW251247R0JNEG)
R75  ValueDisplayed: 10.0k  [0603]  (hidden comment: ERJ-3EKF1002V)
R76  ValueDisplayed: 1.00k  [0603]  (hidden comment: RG1608P-102-B-T5)
R77  ValueDisplayed: 1.6k  [0603]  (hidden comment: CRCW06031K60JNEA)
R78  ValueDisplayed: 1.0M  [0603]  (hidden comment: CRCW06031M00JNEA)
R79  ValueDisplayed: 1.00k  [0603]  (hidden comment: RG1608P-102-B-T5)
R80  ValueDisplayed: 10.0k  [0603]  (hidden comment: ERJ-3EKF1002V)
R81  ValueDisplayed: 47  [2512]  (hidden comment: CRCW251247R0JNEG)
R82  ValueDisplayed: 10.0k  [0603]  (hidden comment: ERJ-3EKF1002V)
R83  ValueDisplayed: 10.0k  [0603]  (hidden comment: ERJ-3EKF1002V)
R84  ValueDisplayed: 1.47k  [0603]  (hidden comment: CRCW06031K47FKEA)
R85  ValueDisplayed: 1.47k  [0603]  (hidden comment: CRCW06031K47FKEA)
R86  ValueDisplayed: 100k  [0603]  (hidden comment: CRCW0603100KFKEA)
R87  ValueDisplayed: 1.00k  [0603]  (hidden comment: RG1608P-102-B-T5)
R88  ValueDisplayed: 100  [0603]  (hidden comment: CRCW0603100RJNEA)
R89  ValueDisplayed: 1.82k  [0603]  (hidden comment: CRCW06031K82FKEA)
R90  ValueDisplayed: 1.0M  [0603]  (hidden comment: CRCW06031M00JNEA)
R91  ValueDisplayed: 1.82k  [0603]  (hidden comment: CRCW06031K82FKEA)
R92  ValueDisplayed: 1.00k  [0603]  (hidden comment: RG1608P-102-B-T5)
R93  ValueDisplayed: 47  [2512]  (hidden comment: CRCW251247R0JNEG)
R94  ValueDisplayed: 0  [0603]  (hidden comment: CRCW06030000Z0EA)
R95  ValueDisplayed: 1.00k  [0603]  (hidden comment: RG1608P-102-B-T5)
R96  ValueDisplayed: 0  [0603]  (hidden comment: CRCW06030000Z0EA)
R97  ValueDisplayed: 1.0M  [0603]  (hidden comment: CRCW06031M00JNEA)
R98  ValueDisplayed: 1.00k  [0603]  (hidden comment: RG1608P-102-B-T5)
R99  ValueDisplayed: 0  [0603]  (hidden comment: CRCW06030000Z0EA)
R100  ValueDisplayed: 47  [2512]  (hidden comment: CRCW251247R0JNEG)
R101  ValueDisplayed: 0  [0603]  (hidden comment: CRCW06030000Z0EA)
R102  ValueDisplayed: 1.00k  [0603]  (hidden comment: RG1608P-102-B-T5)
R103  ValueDisplayed: 0  [0603]  (hidden comment: CRCW06030000Z0EA)
R104  ValueDisplayed: 0  [0603]  (hidden comment: CRCW06030000Z0EA)
R105  ValueDisplayed: 0  [0603]  (hidden comment: CRCW06030000Z0EA)
R106  ValueDisplayed: 0  [0603]  (hidden comment: CRCW06030000Z0EA)
R107  ValueDisplayed: 1.0M  [0603]  (hidden comment: CRCW06031M00JNEA)
R108  ValueDisplayed: 0  [0603]  (hidden comment: CRCW06030000Z0EA)
R109  ValueDisplayed: 1.00k  [0603]  (hidden comment: RG1608P-102-B-T5)
R110  ValueDisplayed: 47  [2512]  (hidden comment: CRCW251247R0JNEG)
R111  ValueDisplayed: 1.00k  [0603]  (hidden comment: RG1608P-102-B-T5)
R112  ValueDisplayed: 1.0M  [0603]  (hidden comment: CRCW06031M00JNEA)
RT1  value 10.0k ohm  [0603]  (hidden comment: ERT-J1VG103FA)
RT2  value 10.0k ohm  [0603]  (hidden comment: ERT-J1VG103FA)
TP-1  5015  [Testpoint_Keystone_Miniature]  (value not drawn)
TP-2  5015  [Testpoint_Keystone_Miniature]  (value not drawn)
TP-3  5015  [Testpoint_Keystone_Miniature]  (value not drawn)
TP-4  5015  [Testpoint_Keystone_Miniature]  (value not drawn)
TP-5  5015  [Testpoint_Keystone_Miniature]  (value not drawn)
TP-6  5015  [Testpoint_Keystone_Miniature]  (value not drawn)
TP-C1  5015  [Testpoint_Keystone_Miniature]  (value not drawn)
TP-C2  5015  [Testpoint_Keystone_Miniature]  (value not drawn)
TP-VPROG1  5015  [Testpoint_Keystone_Miniature]  (value not drawn)
TP-VSS1  5015  [Testpoint_Keystone_Miniature]  (value not drawn)
U1  BQ76PL536ATPAPRQ1  [PAP0064F_N]
Z1  value 36V  [SMA]  (hidden comment: SMAJ36CA)
Z2  value 5.6V  [SOD-123]  (hidden comment: MMSZ5232B-7-F)
Z3  value 5.6V  [SOD-123]  (hidden comment: MMSZ5232B-7-F)
Z4  value 5.6V  [SOD-123]  (hidden comment: MMSZ5232B-7-F)
Z5  value 5.6V  [SOD-123]  (hidden comment: MMSZ5232B-7-F)
Z6  value 5.6V  [SOD-123]  (hidden comment: MMSZ5232B-7-F)
Z7  value 5.6V  [SOD-123]  (hidden comment: MMSZ5232B-7-F)
Z8  value 5.6V  [SOD-123]  (hidden comment: MMSZ5232B-7-F)
Z9  value 5.6V  [SOD-123]  (hidden comment: MMSZ5232B-7-F)
Z10  value 5.6V  [SOD-123]  (hidden comment: MMSZ5232B-7-F)
Z11  value 5.6V  [SOD-123]  (hidden comment: MMSZ5232B-7-F)
Z12  value 5.6V  [SOD-123]  (hidden comment: MMSZ5232B-7-F)
Z13  value 5.6V  [SOD-123]  (hidden comment: MMSZ5232B-7-F)

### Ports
1-ALERT, 1-ALERT_N, 1-ALERT_S, 1-CELL0, 1-CELL1, 1-CELL2, 1-CELL3, 1-CELL4, 1-CELL5, 1-CELL6, 1-CONV, 1-CONV_N, 1-CONV_S, 1-CS_N, 1-CS_S, 1-DRDY, 1-DRDY_N, 1-DRDY_S, 1-FAULT, 1-FAULT_N, 1-FAULT_S, 1-LDOA, 1-LDOD1, 1-REG50, 1-SCLK_N, 1-SCLK_S, 1-SDI_N, 1-SDI_S, 1-SDO_N, 1-SDO_S, 1-SPI-MISO, 1-SPI-MOSI, 1-SPI-SCLK, 1-SPI-SS, 1-VBAT

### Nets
1-VC0: C14.2 C16.2 C18.2 C21.2 C26.2 C29.2 C31.2 C32.2 C39.2 C40.2 C41.2 C42.2 C43.2 C44.2 C45.2 C46.2 C47.2 Q2.4(S) Q2.7(S) Q5.4(S) Q5.7(S) Q8.4(S) Q8.7(S) R75.1 R80.2 R82.2 R83.2 R96.1 R101.2 R103.1 R104.1 R105.1 R108.2 R112.1 TP-VSS1.1 U1.13(VC0) U1.14(VSS) U1.15(AGND) U1.25(VSSD) U1.33(VSS) U1.34(VSS) U1.35(VSS) U1.49(VSSD) U1.50(TEST) U1.65(PAD) Z1.1 Z12.2(A) Z13.2(A) ; port 1-CELL0  [also labelled 1-VSS]
1-ALERT: U1.38(ALERT_H) ; port 1-ALERT
1-ALERT_N: C37.1 U1.57(ALERT_N) ; port 1-ALERT_N
1-ALERT_S: U1.23(ALERT_S) ; port 1-ALERT_S
1-CB1: R111.1 U1.12(CB1)
1-CB2: R102.1 U1.10(CB2)
1-CB3: R95.1 U1.8(CB3)
1-CB4: R87.1 U1.6(CB4)
1-CB5: R76.1 U1.4(CB5)
1-CB6: R69.1 U1.2(CB6)
1-CELL1: C34.2 C42.1 Q7.4(S) Q7.7(S) R107.1 R109.2 R110.2 Z10.2(A) Z11.2(A) Z12.1(K) ; port 1-CELL1
1-CELL2: C28.2 C34.1 Q6.4(S) Q6.7(S) R97.1 R98.2 R100.2 Z8.2(A) Z9.2(A) Z10.1(K) ; port 1-CELL2
1-CELL3: C25.2 C28.1 Q4.4(S) Q4.7(S) R90.1 R92.2 R93.2 Z6.2(A) Z7.2(A) Z8.1(K) ; port 1-CELL3
1-CELL4: C20.2 C25.1 Q3.4(S) Q3.7(S) R78.1 R79.2 R81.2 Z4.2(A) Z5.2(A) Z6.1(K) ; port 1-CELL4
1-CELL5: C17.2 C20.1 Q1.4(S) Q1.7(S) R71.1 R72.2 R74.2 Z2.2(A) Z3.2(A) Z4.1(K) ; port 1-CELL5
1-CELL6: C17.1 J1.1 R66.2 R67.2 TP-C1.1 Z2.1(K) ; port 1-CELL6
1-CONV: R83.1 U1.36(CONV_H) ; port 1-CONV
1-CONV_N: U1.59(CONV_N) ; port 1-CONV_N
1-CONV_S: U1.21(CONV_S) ; port 1-CONV_S
1-CS_N: R105.2 U1.52(CS_N) ; port 1-CS_N
1-CS_S: U1.29(CS_S) ; port 1-CS_S
1-DRDY: U1.37(DRDY_H) ; port 1-DRDY
1-DRDY_N: C38.1 U1.58(DRDY_N) ; port 1-DRDY_N
1-DRDY_S: U1.22(DRDY_S) ; port 1-DRDY_S
1-FAULT: U1.39(FAULT_H) ; port 1-FAULT
1-FAULT_N: C36.1 U1.56(FAULT_N) ; port 1-FAULT_N
1-FAULT_S: U1.24(FAULT_S) ; port 1-FAULT_S
1-LDOA: C44.1 C45.1 U1.17(LDOA) ; port 1-LDOA
1-LDOD1: C46.1 C47.1 R70.2 R94.2 TP-VPROG1.1 U1.18(LDOD1) U1.46(LDOD2) ; port 1-LDOD1
1-REG50: C22.1 C23.1 C43.1 J2.2 J3.2 R77.2 R86.2 RT1.2 RT2.2 U1.32(REG50) ; port 1-REG50
1-SCLK_N: R103.2 U1.55(SCLK_N) ; port 1-SCLK_N
1-SCLK_S: U1.26(SCLK_S) ; port 1-SCLK_S
1-SDI_N: R104.2 U1.53(SDI_N) ; port 1-SDI_N
1-SDI_S: U1.28(SDI_S) ; port 1-SDI_S
1-SDO_N: C35.1 U1.54(SDO_N) ; port 1-SDO_N
1-SDO_S: U1.27(SDO_S) ; port 1-SDO_S
1-SPI-MISO: U1.41(SDO_H) ; port 1-SPI-MISO
1-SPI-MOSI: R82.1 U1.42(SDI_H) ; port 1-SPI-MOSI
1-SPI-SCLK: R80.1 U1.40(SCLK_H) ; port 1-SPI-SCLK
1-SPI-SS: R73.1 ; port 1-SPI-SS
1-VBAT: C16.1 C35.2 C36.2 C37.2 C38.2 C41.1 R68.2 U1.63(BAT1) U1.64(BAT2) Z1.2 ; port 1-VBAT
1-VC1: C30.2 C40.1 R109.1 U1.11(VC1)
1-VC2: C27.2 C29.1 C30.1 R98.1 U1.9(VC2)
1-VC3: C24.2 C26.1 C27.1 R92.1 U1.7(VC3)
1-VC4: C19.2 C21.1 C24.1 R79.1 U1.5(VC4)
1-VC5: C15.2 C18.1 C19.1 R72.1 U1.3(VC5)
1-VC6: C14.1 C15.1 R67.1 U1.1(VC6)
NetC22_2: C22.2 R84.1 R89.2 TP-2.1 U1.20(TS1+)
NetC23_2: C23.2 R85.1 R91.2 TP-4.1 U1.61(TS2+)
NetC31_1: C31.1 C33.2 R106.1 R108.1 U1.47(GPAI-)
NetC32_1: C32.1 C33.1 R99.1 R101.1 U1.48(GPAI+)
NetC39_1: C39.1 U1.16(VREF)
NetD1_1: D1.1(A) R77.1
NetD1_2: D1.2(K) Q5.1(D) Q5.2(D) Q5.5(D) Q5.6(D) Q5.8(D)
NetJ1_2: J1.2 R68.1 TP-C2.1
NetJ2_1: J2.1 R84.2 RT1.1
NetJ3_1: J3.1 R85.2 RT2.1
NetQ1_1: Q1.1(D) Q1.2(D) Q1.5(D) Q1.6(D) Q1.8(D) R66.1
NetQ1_3: Q1.3(G) R69.2 R71.2 Z3.1(K)
NetQ2_1: Q2.1(D) Q2.2(D) Q2.5(D) Q2.6(D) Q2.8(D) R70.1 U1.43(CS_H)
NetQ2_3: Q2.3(G) R73.2 R75.2
NetQ3_1: Q3.1(D) Q3.2(D) Q3.5(D) Q3.6(D) Q3.8(D) R74.1
NetQ3_3: Q3.3(G) R76.2 R78.2 Z5.1(K)
NetQ4_1: Q4.1(D) Q4.2(D) Q4.5(D) Q4.6(D) Q4.8(D) R81.1
NetQ4_3: Q4.3(G) R87.2 R90.2 Z7.1(K)
NetQ5_3: Q5.3(G) R88.1
NetQ6_1: Q6.1(D) Q6.2(D) Q6.5(D) Q6.6(D) Q6.8(D) R93.1
NetQ6_3: Q6.3(G) R95.2 R97.2 Z9.1(K)
NetQ7_1: Q7.1(D) Q7.2(D) Q7.5(D) Q7.6(D) Q7.8(D) R100.1
NetQ7_3: Q7.3(G) R102.2 R107.2 Z11.1(K)
NetQ8_1: Q8.1(D) Q8.2(D) Q8.5(D) Q8.6(D) Q8.8(D) R110.1
NetQ8_3: Q8.3(G) R111.2 R112.2 Z13.1(K)
NetR86_1: R86.1 R88.2 U1.45(GPIO)
NetR89_1: R89.1 TP-3.1 U1.19(TS1-)
NetR91_1: R91.1 TP-1.1 U1.60(TS2-)
NetR94_1: R94.1 R96.2 U1.44(HSEL)
NetR99_2: R99.2 TP-5.1
NetR106_2: R106.2 TP-6.1

Not connected (* = marked no-connect by the designer): U1 30(NC)* 31(AUX)* 51(NC)* 62(NC)*

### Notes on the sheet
- CELL 6 +
- (near RT1) T1
- (near RT2) T2
- S
- H

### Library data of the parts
C14 C17 C18 C20 C21 C25 C26 C28 C29 C40-C42 C44 C46 = 06035C104KAT2A: CAP, CERM, 0.1 µF, 50 V, +/- 10%, X7R, 0603; Manufacturer: AVX; Polarized: N; CompType: Capacitor; Value: 0.1uF; U/M: EA; Cap_F: 0.0000001; Tolerance_%: 10; Value1: Unknown; VDC_V: 50; Value2: 50V; TaMin_C: -55; TaMax_C: 125
C15 C16 C19 C24 C27 C30 C34 = GRM188R72A104KA35D: CAP, CERM, 0.1 µF, 100 V, +/- 10%, X7R, 0603; Manufacturer: MuRata; Polarized: N; CompType: Capacitor; Value: 0.1uF; U/M: EA; Cap_F: 0.0000001; Tolerance_%: 10; Value1: Unknown; VDC_V: 100; Value2: 100V; TaMin_C: -55; TaMax_C: 125
C22 C23 = GRM188R71C473KA01D: CAP, CERM, 0.047 µF, 16 V, +/- 10%, X7R, 0603; Manufacturer: MuRata; Polarized: N; CompType: Capacitor; Value: 0.047uF; U/M: EA; Cap_F: 0.000000047; Tolerance_%: 10; Value1: Unknown; VDC_V: 16; Value2: 16V; TaMin_C: -55; TaMax_C: 125
C31-C33 = C0603C104K4RACTU: CAP, CERM, 0.1 µF, 16 V, +/- 10%, X7R, 0603; Manufacturer: Kemet; Polarized: N; CompType: Capacitor; Value: 0.1uF; U/M: EA; Cap_F: 0.0000001; Tolerance_%: 10; Value1: Unknown; VDC_V: 16; Value2: 16V; TaMin_C: -55; TaMax_C: 125
C35-C38 = GRM1885C1H330JA01D: CAP, CERM, 33 pF, 50 V, +/- 5%, C0G/NP0, 0603; Manufacturer: MuRata; Polarized: N; CompType: Capacitor; Value: 33pF; U/M: EA; Cap_F: 0.000000000033; Tolerance_%: 5; Value1: Unknown; VDC_V: 50; Value2: 50V; TaMin_C: -55; TaMax_C: 125
C39 = C2012X7R1A106M125AC: CAP, CERM, 10 µF, 10 V, +/- 20%, X7R, 0805; Manufacturer: TDK; Polarized: N; CompType: Capacitor; Value: 10uF; U/M: EA; Cap_F: 0.00001; Tolerance_%: 20; Value1: Unknown; VDC_V: 10; Value2: 10V; TaMin_C: -55; TaMax_C: 125; Cap_Case: 0805
C43 C45 C47 = GRM21BR71A225KA01L: CAP, CERM, 2.2 µF, 10 V, +/- 10%, X7R, 0805; Manufacturer: MuRata; Polarized: N; CompType: Capacitor; Value: 2.2uF; U/M: EA; Cap_F: 0.0000022; Tolerance_%: 10; ESR_ohm: 0.006; Value1: 0.006 ohm; Value2: 10V; TaMin_C: -55; TaMax_C: 125; Cap_Case: 0805
D1 = APT1608SYCK: LED, Yellow, SMD; Manufacturer: Kingbright; SymbolCreator: Altium; Vf_V: 2.5; Value2: 2.5V; Io_A: 0.02; Vr_V: 5; Ir_A: 1e-005; Tjmax_C: 85; Value1: W; Angle: 120; U/M: EA
J1-J3 = PEC02SAAN: as JP1 on sheet PWR763A_1
Q1-Q8 = CSD16301Q2: MOSFET, N-CH, 25 V, 5 A, SON 2x2mm; Manufacturer: Texas Instruments; Alternate Manufacturer: None; U/M: EA; ChType: N; Value: 25V; VdsMax_V: 25; Value1: 0.023 ohm; Rdson45_ohm: 0.023; Value2: 2 nC; QgTyp_nC: 2; Vgs_V: 10; IdsMax_A: 5
R66 R74 R81 R93 R100 R110 = CRCW251247R0JNEG: RES, 47, 5%, 1 W, 2512; Manufacturer: Vishay-Dale; CompType: Resistor; Value: 47; Value_Code: 47R0; Tolerance_%: 5; Power_W: 1; Value2: 1W; VDC_V: 500; TempCo: 200 ppm/C; EIA_Code: E24; U/M: EA
R67 R69 R72 R73 R76 R79 R87 R92 R95 R98 R102 R109 R111 = RG1608P-102-B-T5: as R21 on sheet PWR763A_1
R68 = CRCW08050000Z0EA: RES, 0, 5%, 0.125 W, 0805; Manufacturer: Vishay-Dale; CompType: Resistor; Value: 0; Value_Code: 0000; Tolerance_%: 5; Power_W: 0.125; Value2: 0.125W; VDC_V: 150; TempCo: 200 ppm/C; EIA_Code: E24; U/M: EA
R70 R75 R80 R82 R83 = ERJ-3EKF1002V: RES, 10.0 k, 1%, 0.1 W, 0603; Manufacturer: Panasonic; CompType: Resistor; Value: 10.0k; Res_ohm: 10000; Value_Code: 10k0; Tolerance_%: 1; Power_W: 0.1; Value2: 0.1W; VDC_V: 75; TempCo: 100 ppm/C; EIA_Code: E96; U/M: EA
R71 R78 R90 R97 R107 R112 = CRCW06031M00JNEA: RES, 1.0 M, 5%, 0.1 W, 0603; Manufacturer: Vishay-Dale; CompType: Resistor; Value: 1.0Meg; Res_ohm: 1000000; Value_Code: 1M00; Tolerance_%: 5; Power_W: 0.1; Value2: 0.1W; VDC_V: 75; TempCo: 200 ppm/C; EIA_Code: E24; U/M: EA
R77 = CRCW06031K60JNEA: RES, 1.6 k, 5%, 0.1 W, 0603; Manufacturer: Vishay-Dale; CompType: Resistor; Value: 1.6k; Res_ohm: 1600; Value_Code: 1k60; Tolerance_%: 5; Power_W: 0.1; Value2: 0.1W; VDC_V: 75; TempCo: 200 ppm/C; EIA_Code: E24; U/M: EA
R84 R85 = CRCW06031K47FKEA: RES, 1.47 k, 1%, 0.1 W, 0603; Manufacturer: Vishay-Dale; CompType: Resistor; Value: 1.47k; Res_ohm: 1470; Value_Code: 1k47; Tolerance_%: 1; Power_W: 0.1; Value2: 0.1W; VDC_V: 75; TempCo: 100 ppm/C; EIA_Code: E96; U/M: EA
R86 = CRCW0603100KFKEA: RES, 100 k, 1%, 0.1 W, 0603; Manufacturer: Vishay-Dale; CompType: Resistor; Value: 100k; Res_ohm: 100000; Tolerance_%: 1; Power_W: 0.1; Value2: 0.1W; VDC_V: 75; TempCo: 100 ppm/C; EIA_Code: E96; U/M: EA
R88 = CRCW0603100RJNEA: RES, 100, 5%, 0.1 W, 0603; Manufacturer: Vishay-Dale; CompType: Resistor; Value: 100; Value_Code: 100R; Tolerance_%: 5; Power_W: 0.1; Value2: 0.1W; VDC_V: 75; TempCo: 200 ppm/C; EIA_Code: E24; U/M: EA
R89 R91 = CRCW06031K82FKEA: RES, 1.82 k, 1%, 0.1 W, 0603; Manufacturer: Vishay-Dale; CompType: Resistor; Value: 1.82k; Res_ohm: 1820; Value_Code: 1k82; Tolerance_%: 1; Power_W: 0.1; Value2: 0.1W; VDC_V: 75; TempCo: 100 ppm/C; EIA_Code: E96; U/M: EA
R94 R96 R99 R101 R103-R106 R108 = CRCW06030000Z0EA: as R2 on sheet PWR763A_1
RT1 RT2 = ERT-J1VG103FA: Thermistor NTC, 10.0k ohm, 1%, 0603; Manufacturer: Panasonic; Tolerance_%: 1; Power_W: 0.1; TaMin_C: -40; TaMax_C: 125; U/M: EA
TP-1-TP-6 TP-C1 TP-C2 TP-VPROG1 TP-VSS1 = 5015: as TP1 on sheet PWR763A_1
U1 = BQ76PL536ATPAPRQ1: 3 to 6 Series Cell Lithium-Ion Battery Monitor and Secondary Protection IC for EV and HEV Application, PAP0064F; Alternate PartNumber: BQ76PL536ATPAPTQ1; Manufacturer: Texas Instruments; SymbolCreator: Altium; U/M: EA
Z1 = SMAJ36CA: Diode, TVS, Bi, 36 V, 400 W, SMA; Manufacturer: Littelfuse; U/M: EA; Power_W: 400; Vr_V: 36; Value1: 400W; RJA_CperW: 120
Z2-Z13 = MMSZ5232B-7-F: Diode, Zener, 5.6 V, 500 mW, SOD-123; Manufacturer: Diodes Inc.; SymbolCreator: a0412235; U/M: EA; Power_W: 0.5; Vz_V: 5.6; Value1: 0.5W; RJA_CperW: 350; AEC Category: Q101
